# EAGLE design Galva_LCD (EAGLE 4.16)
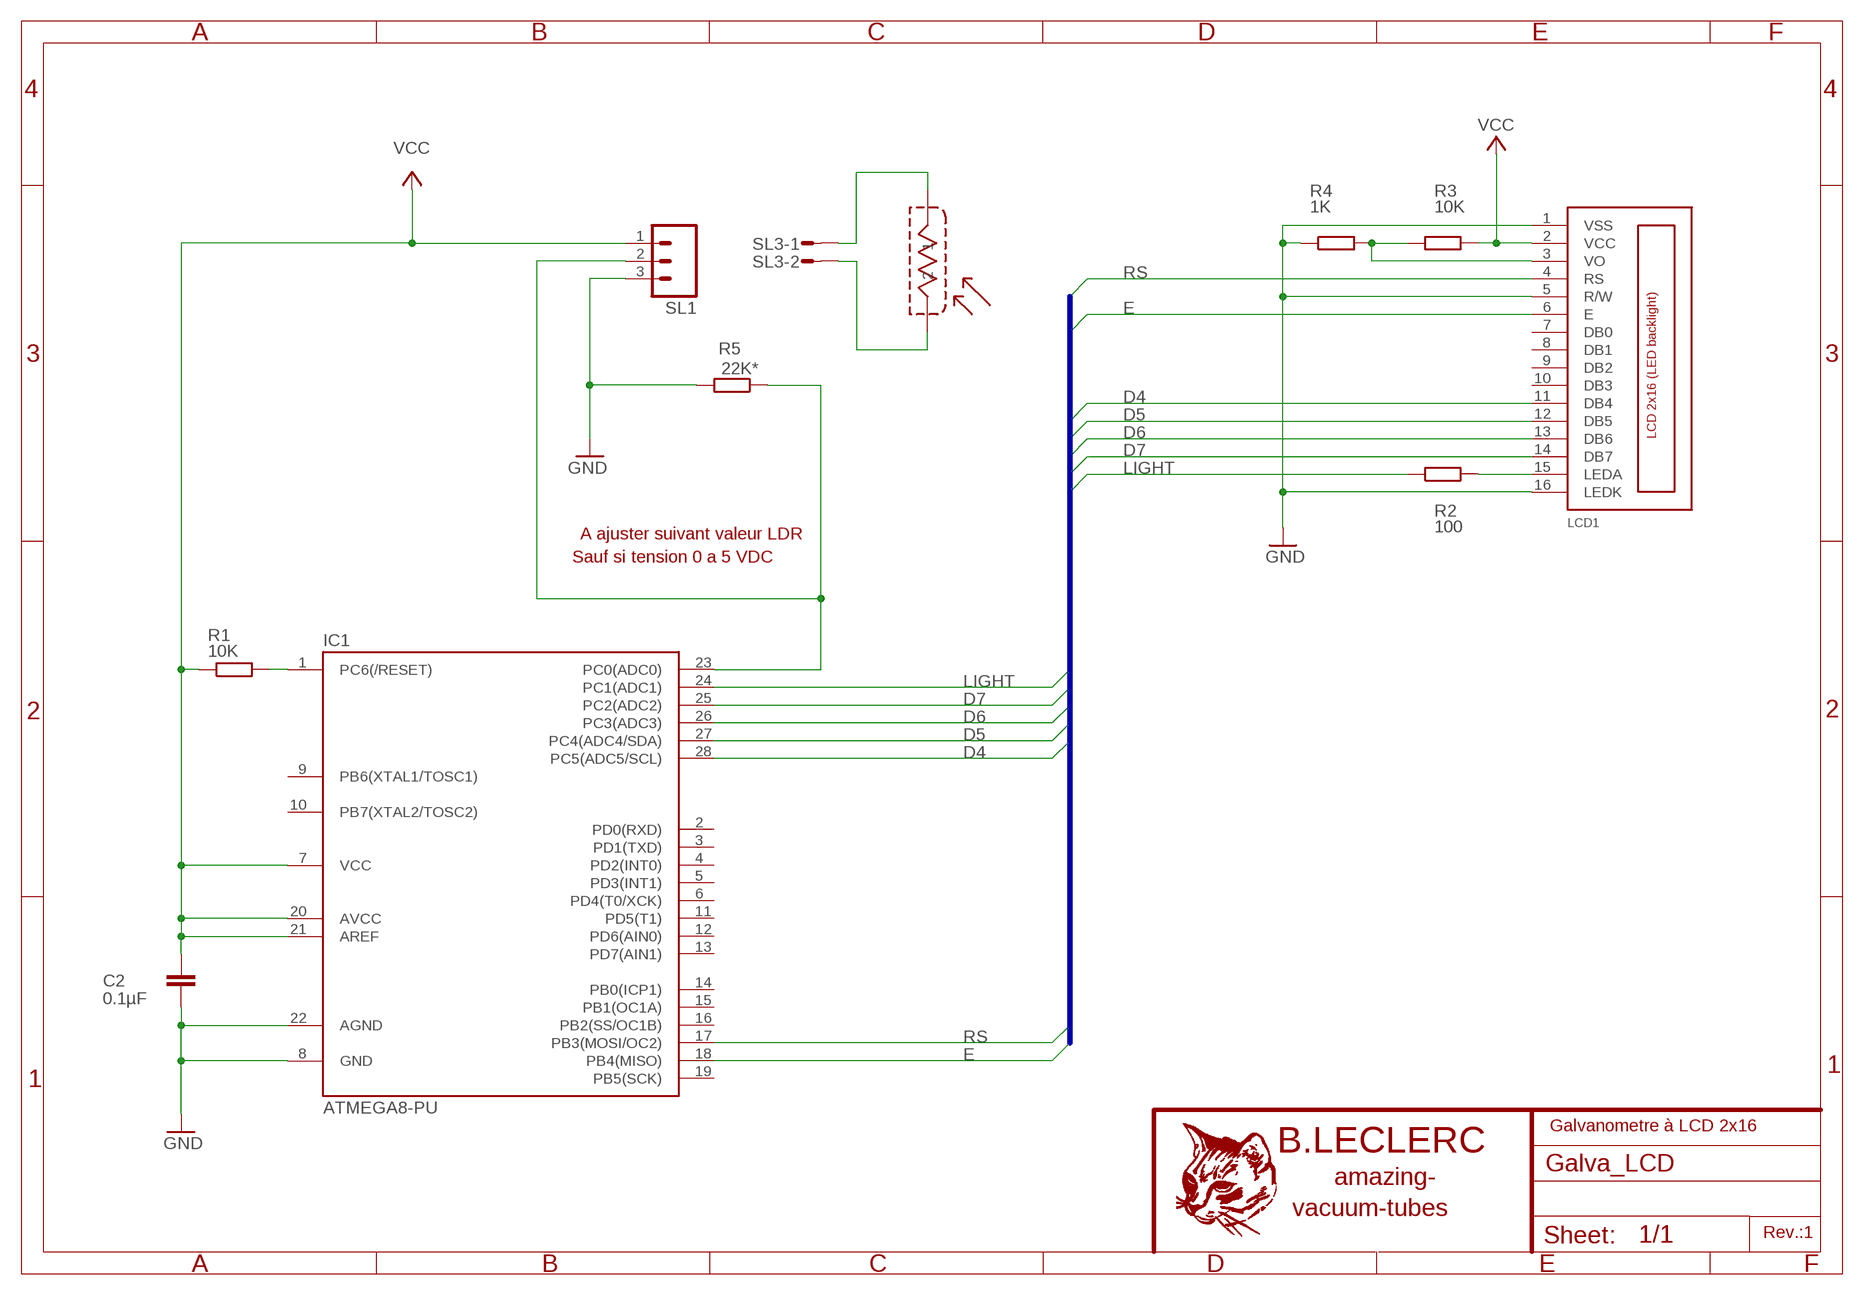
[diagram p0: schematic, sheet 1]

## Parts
C2  0.1µF  C-EU050-025X075  [C050-025X075]
IC1  ATMEGA8-PU  [DIL28-3]
LCD1  LCD_2X16_SIL  [HY-1602F]
LDR1  LDR  [LDR]
R1  10K  R-EU_0207/10  [0207/10]
R2  100  R-EU_0207/10  [0207/10]
R3  10K  R-EU_0207/10  [0207/10]
R4  1K  R-EU_0207/10  [0207/10]
R5  22K*  R-EU_0207/10  [0207/10]
SL1  M03  [03P]
SL3  M02S  [02P]

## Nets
D4: IC1.28(PC5(ADC5/SCL)) LCD1.11(DB4)
D5: IC1.27(PC4(ADC4/SDA)) LCD1.12(DB5)
D6: IC1.26(PC3(ADC3)) LCD1.13(DB6)
D7: IC1.25(PC2(ADC2)) LCD1.14(DB7)
E: IC1.18(PB4(MISO)) LCD1.6(E)
GND: C2.2 IC1.8(GND) IC1.22(AGND) LCD1.1(VSS) LCD1.5(R/W) LCD1.16(LEDK) R4.1 R5.2 SL1.3
LIGHT: IC1.24(PC1(ADC1)) R2.1
N$1: LDR1.2 SL3.1
N$2: LDR1.1 SL3.2
N$3: IC1.1(PC6(/RESET)) R1.2
N$4: LCD1.3(VO) R3.1 R4.2
N$5: LCD1.15(LEDA) R2.2
N$11: IC1.23(PC0(ADC0)) R5.1 SL1.2
RS: IC1.17(PB3(MOSI/OC2)) LCD1.4(RS)
VCC: C2.1 IC1.7(VCC) IC1.20(AVCC) IC1.21(AREF) LCD1.2(VCC) R1.1 R3.2 SL1.1
Unconnected: IC1.2(PD0(RXD)) IC1.3(PD1(TXD)) IC1.4(PD2(INT0)) IC1.5(PD3(INT1)) IC1.6(PD4(T0/XCK)) IC1.9(PB6(XTAL1/TOSC1)) IC1.10(PB7(XTAL2/TOSC2)) IC1.11(PD5(T1)) IC1.12(PD6(AIN0)) IC1.13(PD7(AIN1)) IC1.14(PB0(ICP1)) IC1.15(PB1(OC1A)) IC1.16(PB2(SS/OC1B)) IC1.19(PB5(SCK)) LCD1.7(DB0) LCD1.8(DB1) LCD1.9(DB2) LCD1.10(DB3)

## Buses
B$1

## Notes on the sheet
- A ajuster suivant valeur LDR
- Sauf si tension 0 a 5 VDC
- Galvanometre à LCD 2x16
- Rev.:1

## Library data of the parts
C2 = rcl:C-EU: CAPACITOR, European symbol
IC1 = atmega8:ATMEGA8-PU
LCD1 = lcd_2x16_led_backlight:LCD_2X16_SIL
LDR1 = special:LDR
R1-R5 = rcl:R-EU_: RESISTOR, European symbol
SL1 = con-NANARD:M03: AMP QUICK CONNECTOR
SL3 = con-NANARD:M02S: AMP QUICK CONNECTOR

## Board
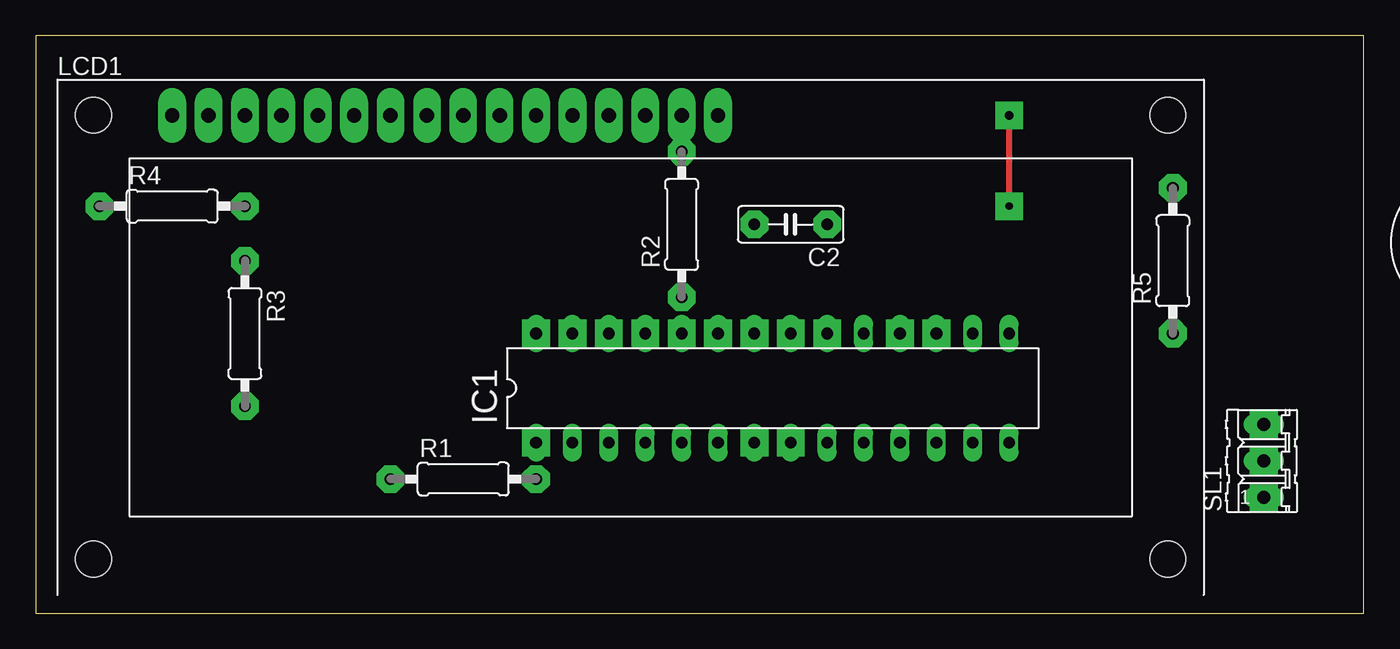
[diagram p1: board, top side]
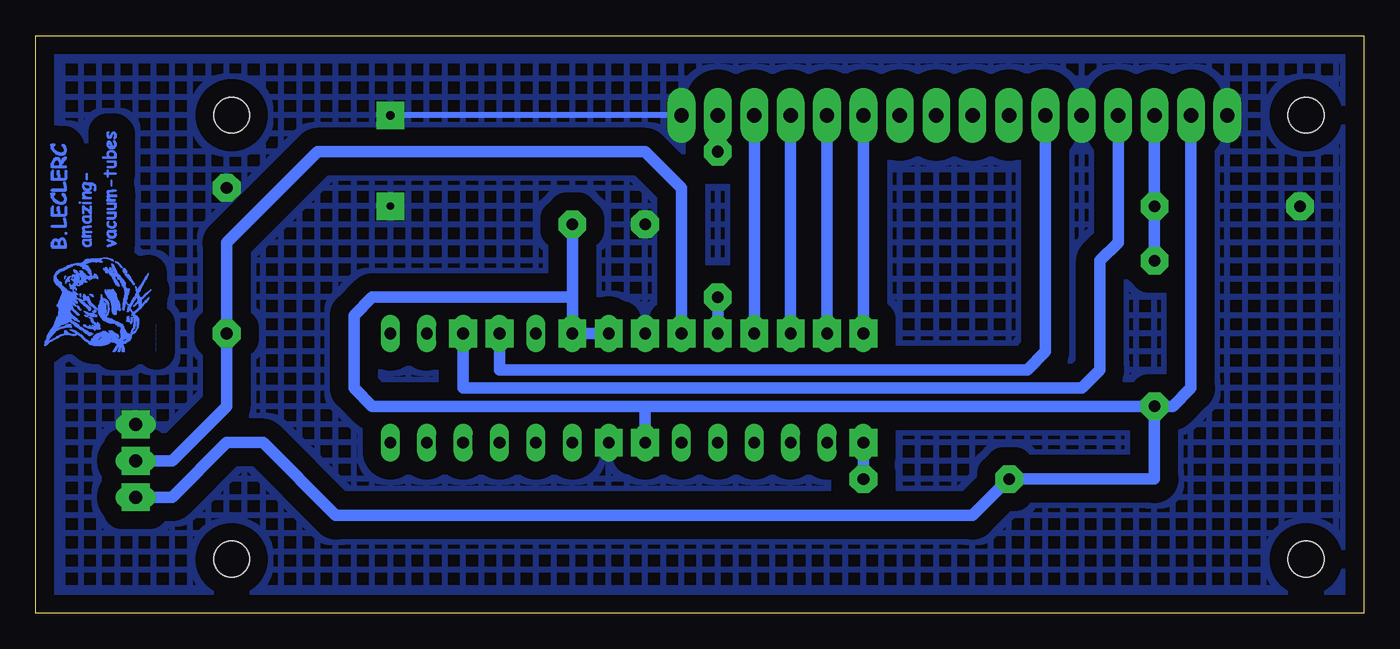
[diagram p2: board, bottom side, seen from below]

Size 92.69 x 40.31 mm. Coordinates in mm from the lower left corner, seen from the top.
Outline: 0,0 92.69,0 92.69,40.31 0,40.31 0,0
Copper layers (1*16): Top 0.035mm / dielectric 1.5mm / Bottom 0.035mm
Design rules "default": minimum track width 10mil, minimum drill 24mil, track to track 8mil, track to pad 8mil, pad to pad 8mil, via to via 8mil, smd to smd 8mil, copper to edge 40mil, drill to drill 8mil, minimum pad ring 10mil, minimum via ring 8mil, stop-mask expansion 4mil, vias tented up to drill 0mil, thermal gap 10mil

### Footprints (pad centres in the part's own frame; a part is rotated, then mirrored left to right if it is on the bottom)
C050-025X075 = drill 0.813 octagon: 1 -2.54,0; 2 2.54,0
DIL28-3 = drill 0.813 long: 1 -16.51,-3.81; 2 -13.97,-3.81; 3 -11.43,-3.81; 4 -8.89,-3.81; 5 -6.35,-3.81; 6 -3.81,-3.81; 7 -1.27,-3.81; 8 1.27,-3.81; 9 3.81,-3.81; 10 6.35,-3.81; 11 8.89,-3.81; 12 11.43,-3.81; 13 13.97,-3.81; 14 16.51,-3.81; 15 16.51,3.81; 16 13.97,3.81; 17 11.43,3.81; 18 8.89,3.81; 19 6.35,3.81; 20 3.81,3.81; 21 1.27,3.81; 22 -1.27,3.81; 23 -3.81,3.81; 24 -6.35,3.81; 25 -8.89,3.81; 26 -11.43,3.81; 27 -13.97,3.81; 28 -16.51,3.81
HY-1602F = drill 1 pad 1.93 long: 1 2.54,0; 2 5.08,0; 3 7.62,0; 4 10.16,0; 5 12.7,0; 6 15.24,0; 7 17.78,0; 8 20.32,0; 9 22.86,0; 10 25.4,0; 11 27.94,0; 12 30.48,0; 13 33.02,0; 14 35.56,0; 15 38.1,0; 16 40.64,0 | hole 2.5: -2.96,0; 72.04,0; -2.96,-31; 72.04,-31
LDR = drill 0.5 pad 1.93 square: 1 -2.54,0; 2 2.54,0
0207/10 = drill 0.813 octagon: 1 -5.08,0; 2 5.08,0
03P = drill 0.914 long: 1 -2.54,0; 2 0,0; 3 2.54,0
02P = drill 0.914 long: 1 -1.27,0; 2 1.27,0

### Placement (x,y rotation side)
C2  52.7,27.14 180 top
IC1  51.43,15.71 0 top
LCD1  6.98,34.76 0 top
LDR1  not placed on the board
R1  29.84,9.36 0 top
R2  45.08,27.14 90 top
R3  14.6,19.52 270 top
R4  9.52,28.41 0 top
R5  79.37,24.6 90 top
SL1  85.72,10.63 90 top
SL3  not placed on the board
U$2  [CHAT]  84.45,18.25 90 bottom

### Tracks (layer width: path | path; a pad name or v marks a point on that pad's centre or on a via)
D4
  Bottom 0.813: IC1.28 LCD1.11
D5
  Bottom 0.813: IC1.27 LCD1.12
D6
  Bottom 0.813: IC1.26 LCD1.13
D7
  Bottom 0.813: IC1.25 LCD1.14
E
  Bottom 0.813: LCD1.6 22.22,18.25 23.49,16.98 60.32,16.98 IC1.18
GND  (via drill 0.5 pad 1.93, 0.6)
  Top 0.406: v67.94,34.76 v67.94,28.41
  Bottom 0.406: LCD1.16 v67.94,34.76
  other vias: 4.44,28.41 50.16,27.14 79.37,29.68 9.52,34.76 19.68,34.76 47.62,34.76 85.72,13.17 50.16,19.52 52.7,11.9
  pour Bottom (isolate 1.27, no thermals, hatched): 0.63,39.84 92.07,39.84 92.07,0.47 0.63,0.47
LIGHT
  Bottom 0.813: IC1.24 R2.1
N$1  (1 unrouted)
N$2  (1 unrouted)
N$3
  Bottom 0.813: R1.2 IC1.1
N$4
  Bottom 0.813: LCD1.3 R4.2 R3.1
N$5
  Bottom 0.813: R2.2 LCD1.15
N$7  (via drill 0.5 pad 1.93)
  other vias: 34.92,19.52
N$8  (via drill 0.5 pad 1.93)
  other vias: 14.6,28.41
N$9  (via drill 0.5 pad 1.93)
  other vias: 14.6,24.6
N$10  (via drill 0.5 pad 1.93)
  other vias: 14.6,14.44
N$11
  Bottom 0.813: IC1.23 47.62,29.68 50.16,32.22 73.02,32.22 79.37,25.87 R5.1 79.37,14.44 83.18,10.63 SL1.2
N$12  (via drill 0.5 pad 1.93)
  other vias: 45.08,32.22
N$13  (via drill 0.5 pad 1.93)
  other vias: 45.08,22.06
N$14  (via drill 0.5 pad 1.93)
  other vias: 12.06,34.76
N$15  (via drill 0.5 pad 1.93)
  other vias: 55.24,27.14
N$16  (via drill 0.5 pad 1.93)
  other vias: 24.76,9.36
N$17  (via drill 0.5 pad 1.93)
  other vias: 34.92,9.36
N$18  (via drill 0.5 pad 1.93)
  other vias: 14.6,34.76
N$19  (via drill 0.5 pad 1.93)
  other vias: 79.37,19.52
N$20  (via drill 0.5 pad 1.93)
  other vias: 17.14,34.76
N$21  (via drill 0.5 pad 1.93)
  other vias: 37.46,19.52
N$22  (via drill 0.5 pad 1.93)
  other vias: 22.22,34.76
N$23  (via drill 0.5 pad 1.93)
  other vias: 34.92,34.76
N$24  (via drill 0.5 pad 1.93)
  other vias: 37.46,34.76
N$25  (via drill 0.5 pad 1.93)
  other vias: 40,34.76
N$26  (via drill 0.5 pad 1.93)
  other vias: 42.54,34.76
N$27  (via drill 0.5 pad 1.93)
  other vias: 45.08,34.76
N$28  (via drill 0.5 pad 1.93)
  other vias: 40,19.52
N$29  (via drill 0.5 pad 1.93)
  other vias: 85.72,8.09
N$30  (via drill 0.5 pad 1.93)
  other vias: 85.72,10.63
N$31  (via drill 0.5 pad 1.93)
  other vias: 42.54,19.52
N$32  (via drill 0.5 pad 1.93)
  other vias: 45.08,19.52
N$33  (via drill 0.5 pad 1.93)
  other vias: 47.62,19.52
N$35  (via drill 0.5 pad 1.93)
  other vias: 52.7,19.52
N$36  (via drill 0.5 pad 1.93)
  other vias: 55.24,19.52
N$37  (via drill 0.5 pad 1.93)
  other vias: 60.32,19.52
N$38  (via drill 0.5 pad 1.93)
  other vias: 62.86,19.52
N$40  (via drill 0.5 pad 1.93)
  other vias: 50.16,11.9
N$41  (via drill 0.5 pad 1.93)
  other vias: 34.92,11.9
RS
  Bottom 0.813: LCD1.4 17.14,25.87 18.41,24.6 18.41,16.98 19.68,15.71 62.86,15.71 IC1.17
VCC
  Bottom 0.813: LCD1.2 12.06,15.71 13.33,14.44 R3.2 | R3.2 14.6,9.36 R1.1 27.3,6.82 71.75,6.82 76.83,11.9 79.37,11.9 83.18,8.09 SL1.1 | IC1.20 IC1.21 IC1.20 | 55.24,22.06 IC1.20 | 50.16,14.44 IC1.7 | R3.2 50.16,14.44 | 55.24,22.06 C2.1 | 55.24,22.06 69.21,22.06 70.48,20.79 70.48,15.71 69.21,14.44 50.16,14.44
